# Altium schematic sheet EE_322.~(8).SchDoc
size A4; SheetNumber: 1; SheetTotal: 1
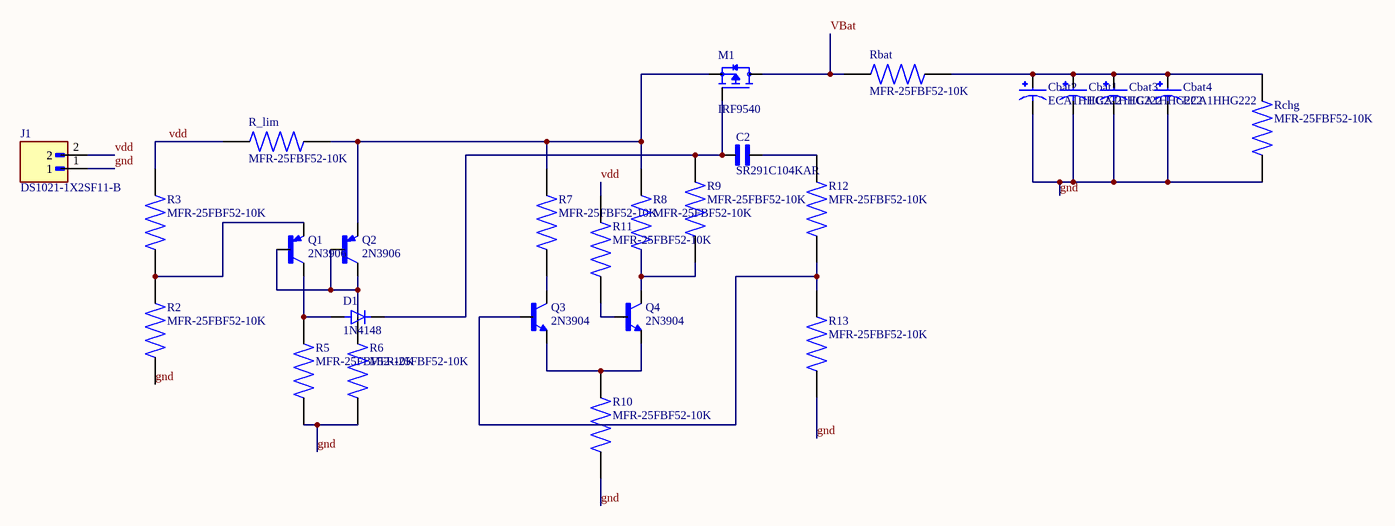
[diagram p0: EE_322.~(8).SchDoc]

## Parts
C2  SR291C104KAR  [CAPRR254W50L508T317H508]
Cbat1  ECA1HHG222  [CAPPRD750W80D1600H3150]
Cbat2  ECA1HHG222  [CAPPRD750W80D1600H3150]
Cbat3  ECA1HHG222  [CAPPRD750W80D1600H3150]
Cbat4  ECA1HHG222  [CAPPRD750W80D1600H3150]
D1  1N4148  [DIOAD753W49L380D172B]
J1  DS1021-1X2SF11-B  [CONNFLY_DS1021-1X2SF11-B]
M1  IRF9540  [TO254P1052X465X1989-3]
Q1  2N3906  [TO92254P460H750-3]
Q2  2N3906  [TO92254P460H750-3]
Q3  2N3904  [TO92254P460H750-3]
Q4  2N3904  [TO92254P460H750-3]
R2  MFR-25FBF52-10K  [RESAD1100W55L680D260]
R3  MFR-25FBF52-10K  [RESAD1100W55L680D260]
R5  MFR-25FBF52-10K  [RESAD1100W55L680D260]
R6  MFR-25FBF52-10K  [RESAD1100W55L680D260]
R7  MFR-25FBF52-10K  [RESAD1100W55L680D260]
R8  MFR-25FBF52-10K  [RESAD1100W55L680D260]
R9  MFR-25FBF52-10K  [RESAD1100W55L680D260]
R10  MFR-25FBF52-10K  [RESAD1100W55L680D260]
R11  MFR-25FBF52-10K  [RESAD1100W55L680D260]
R12  MFR-25FBF52-10K  [RESAD1100W55L680D260]
R13  MFR-25FBF52-10K  [RESAD1100W55L680D260]
R_lim  MFR-25FBF52-10K  [RESAD1100W55L680D260]
Rbat  MFR-25FBF52-10K  [RESAD1100W55L680D260]
Rchg  MFR-25FBF52-10K  [RESAD1100W55L680D260]

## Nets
gnd: Cbat1.N Cbat2.N Cbat3.N Cbat4.N J1.1 R2.1 R5.1 R6.1 R10.1 R13.1 Rchg.1
VBat: M1.2(D) Rbat.2
vdd: J1.2 R3.2 R11.2 R_lim.1
NetC2_1: C2.1 D1.K M1.1(G) R9.2
NetC2_2: C2.2 R12.2
NetCbat1_P: Cbat1.P Cbat2.P Cbat3.P Cbat4.P Rbat.1 Rchg.2
NetD1_A: D1.A Q1.3(C) R5.2
NetM1_3: M1.3(S) Q2.1(E) R7.2 R8.2 R_lim.2
NetQ1_1: Q1.1(E) R2.2 R3.1
NetQ1_2: Q1.2(B) Q2.2(B) Q2.3(C) R6.2
NetQ3_1: Q3.1(E) Q4.1(E) R10.2
NetQ3_2: Q3.2(B) R12.1 R13.2
NetQ3_3: Q3.3(C) R7.1
NetQ4_2: Q4.2(B) R11.1
NetQ4_3: Q4.3(C) R8.1 R9.1

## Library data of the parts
C2 = SR291C104KAR: SR Series 5.08 x 5.08 mm 100 nF 100 V Â±10 % Tol. X7R Radial Lead/SkyCapÂ®; MF: AVX
Cbat1-Cbat4 = ECA1HHG222: Cap Aluminum 2200uF 50V 20% (16 X 31.5mm) Radial Aluminum Cylindrical Can 7.5mm 1470mA 2000 hr 105C Bulk; MF: Panasonic
D1 = 1N4148: Diode Standard 75V 200mA Surface Mount SOD-523F; MF: onsemi
J1 = DS1021-1X2SF11-B: 2 position 2.54mm single row vertical pin header; MF: Connfly
M1 = IRF9540: P-Channel 100 V 19A (Tc) 3.7W (Ta), 150W (Tc) Surface Mount DÂ²PAK (TO-263); MF: Vishay
Q1 Q2 = 2N3906: BJT, TO-92, 40V, 200mA, PNP, 0.625W, 150Â°C; MF: Diotec Semiconductor
Q3 Q4 = 2N3904: BJT, TO-92, 40V, 200mA, NPN, 0.625W, 150Â°C; MF: Diotec Semiconductor
R2 R3 R5-R13 R_lim Rbat Rchg = MFR-25FBF52-10K: 10.2 kOhms Â±1% 0.25W, 1/4W Through Hole Resistor Axial - Metal Film; MF: Yageo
